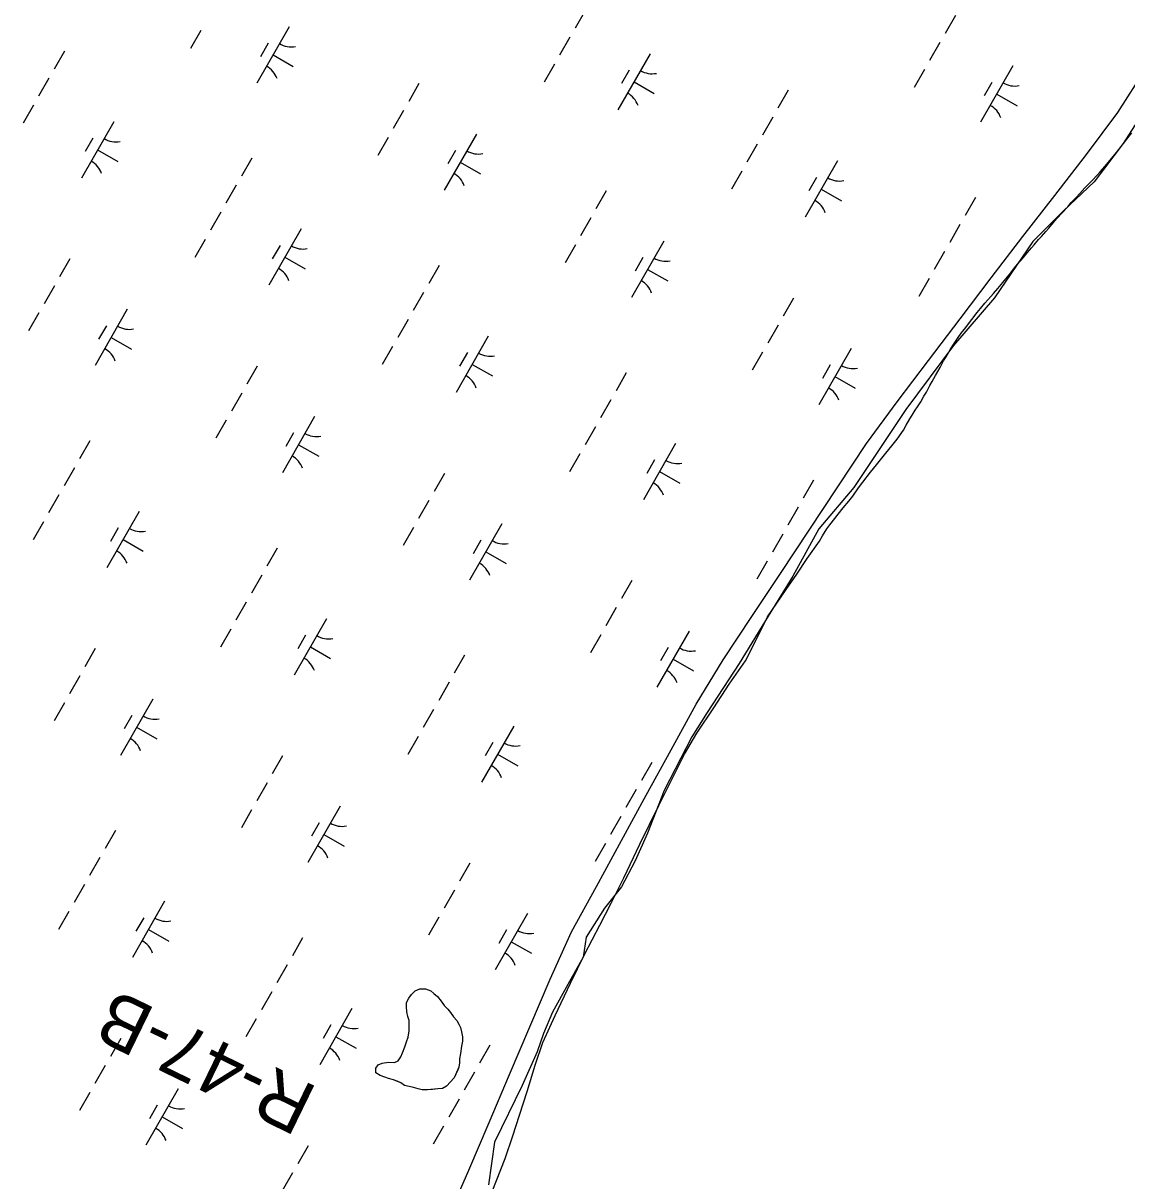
# Model space of a CAD drawing. Extents: x 3930721 to 3950824, y 220441 to 242861.
# Drawn here: x 3937569 to 3938420, y 226313 to 227205 of the extents above; entities that cross this region are included whole.
import ezdxf

# ---------------------------------------------------------------- set-up
doc = ezdxf.new("R2010")
doc.units = 0
for name, color, linetype in [('V-RIVR-EDGE', 7, 'Continuous'), ('V-RIVR-RANG-IDEN', 7, 'Continuous'), ('V-RRAP-FSHR', 7, 'Continuous'), ('V-TOPO-SHOR', 7, 'Continuous'), ('V-WETL-SWMP', 7, 'Continuous')]:
    doc.layers.add(name, color=color, linetype=linetype)

msp = doc.modelspace()

# ---------------------------------------------------------------- linework, layer by layer
at = {"layer": 'V-RIVR-EDGE'}
msp.add_lwpolyline([(3938454.68, 227171.4), (3938416.96, 227112.46), (3938394.57, 227083), (3938370.99, 227060.6), (3938347.42, 227037.03), (3938317.95, 226993.41), (3938286.13, 226956.87), (3938249.59, 226907.37), (3938209.51, 226847.25), (3938182.4, 226815.43), (3938162.36, 226778.89), (3938143.5, 226748.24), (3938121.11, 226711.7), (3938096.35, 226673.98), (3938084.57, 226655.12), (3938063.35, 226613.87), (3938050.38, 226580.86), (3938040.95, 226559.65), (3938030.34, 226539.61), (3938017.38, 226523.11), (3938003.23, 226500.71), (3938000.88, 226485.39), (3937989.09, 226464.17), (3937977.3, 226442.95), (3937970.23, 226426.45), (3937965.52, 226412.31), (3937953.73, 226386.38), (3937932.51, 226342.76), (3937927.8, 226309.76)], dxfattribs=at)
at = {"layer": 'V-RRAP-FSHR'}
msp.add_lwpolyline([(3937896.8, 226284.54), (3937912.71, 226321.23), (3937928.51, 226357.98), (3937944.13, 226394.8), (3937959.75, 226431.63), (3937975.38, 226468.45), (3937991.95, 226504.81), (3938011.14, 226539.91), (3938030.32, 226575.12), (3938049.5, 226610.11), (3938068.68, 226645.21), (3938087.86, 226680.31), (3938108.69, 226714.42), (3938130.77, 226747.78), (3938152.85, 226781.13), (3938174.93, 226814.49), (3938197.13, 226847.84), (3938219.1, 226881.18), (3938242.95, 226913.29), (3938266.92, 226945.32), (3938291.41, 226977.22), (3938315.4, 227008.95), (3938339.77, 227040.67), (3938364.23, 227072.32), (3938388.68, 227103.97), (3938412.83, 227136.41), (3938434.22, 227169.85)], dxfattribs=at)
at = {"layer": 'V-TOPO-SHOR'}
msp.add_lwpolyline([(3937895.57, 226385.81), (3937892.38, 226384.2), (3937888.78, 226383.8), (3937884.79, 226383.39), (3937880.79, 226382.98), (3937876.79, 226382.96), (3937873.59, 226383.76), (3937869.99, 226384.95), (3937866.79, 226385.74), (3937863.19, 226386.52), (3937860.39, 226388.52), (3937857.59, 226389.71), (3937854.79, 226390.9), (3937850.79, 226391.69), (3937847.99, 226392.88), (3937844.39, 226394.07), (3937841.19, 226396.06), (3937841.18, 226399.66), (3937842.77, 226402.46), (3937845.96, 226403.67), (3937850.76, 226404.48), (3937855.56, 226404.09), (3937858.35, 226405.3), (3937860.34, 226408.5), (3937861.53, 226411.7), (3937863.52, 226416.1), (3937864.7, 226420.1), (3937865.89, 226423.7), (3937866.68, 226428.5), (3937866.67, 226432.1), (3937866.66, 226436.49), (3937865.85, 226439.69), (3937865.04, 226443.29), (3937864.63, 226447.28), (3937864.62, 226450.48), (3937866.61, 226453.68), (3937868.6, 226456.49), (3937871.39, 226459.29), (3937874.99, 226460.9), (3937879.38, 226460.91), (3937883.38, 226459.32), (3937885.79, 226457.33), (3937888.59, 226454.94), (3937891.4, 226451.35), (3937893.81, 226448.16), (3937896.61, 226445.37), (3937898.62, 226442.58), (3937901.02, 226439.38), (3937903.43, 226436.59), (3937905.04, 226433.8), (3937906.24, 226431.01), (3937907.05, 226427.81), (3937907.86, 226423.82), (3937907.87, 226420.62), (3937907.08, 226416.62), (3937906.29, 226411.02), (3937905.51, 226407.02), (3937905.51, 226403.82), (3937905.12, 226400.62), (3937903.93, 226397.83), (3937902.74, 226395.02), (3937901.55, 226392.22), (3937895.57, 226385.81)], dxfattribs=at)
at = {"layer": 'V-WETL-SWMP'}
for p, q in [((3938002.57, 227215.37), (3937994.62, 227201.49)), ((3938287.74, 227211.08), (3938279.78, 227197.2)), ((3937706.14, 227199.66), (3937698.19, 227185.77)), ((3937774.26, 227202.47), (3937749.41, 227159.08)), ((3937758.12, 227189.82), (3937752.16, 227179.4)), ((3937990.64, 227194.54), (3937982.69, 227180.66)), ((3938275.81, 227190.25), (3938267.86, 227176.37)), ((3937601.1, 227183.76), (3937593.14, 227169.88)), ((3937761.84, 227180.78), (3937777.45, 227171.83)), ((3938052.47, 227181.7), (3938027.62, 227138.31)), ((3937978.71, 227173.72), (3937970.76, 227159.83)), ((3938036.33, 227169.04), (3938030.37, 227158.63)), ((3938263.88, 227169.43), (3938255.93, 227155.54)), ((3938332, 227172.24), (3938307.15, 227128.85)), ((3937589.17, 227162.93), (3937581.22, 227149.05)), ((3938040.04, 227160), (3938055.66, 227151.06)), ((3938315.86, 227159.59), (3938309.9, 227149.17)), ((3937874.33, 227158.64), (3937866.38, 227144.76)), ((3938158.84, 227153.53), (3938150.89, 227139.65)), ((3938319.58, 227150.55), (3938335.2, 227141.6)), ((3937577.24, 227142.11), (3937569.29, 227128.22)), ((3937862.41, 227137.82), (3937854.45, 227123.93)), ((3938146.91, 227132.7), (3938138.96, 227118.82)), ((3937639.07, 227129.26), (3937614.22, 227085.87)), ((3937622.93, 227116.61), (3937616.96, 227106.19)), ((3937850.48, 227116.99), (3937842.53, 227103.11)), ((3937918.6, 227119.8), (3937893.75, 227076.42)), ((3938417.25, 227112.51), (3938419.83, 227115.77)), ((3938419.83, 227115.77), (3938423.62, 227120.75)), ((3937626.64, 227107.57), (3937642.26, 227098.62)), ((3937902.46, 227107.15), (3937896.5, 227096.74)), ((3938134.98, 227111.88), (3938127.03, 227097.99)), ((3938409.34, 227102.39), (3938411.92, 227105.65)), ((3938411.92, 227105.65), (3938415.36, 227110.11)), ((3938415.36, 227110.11), (3938417.25, 227112.51)), ((3937745.44, 227101.09), (3937737.48, 227087.21)), ((3937906.18, 227098.11), (3937921.8, 227089.17)), ((3938196.81, 227099.03), (3938171.96, 227055.64)), ((3938402.98, 227094.84), (3938405.56, 227097.76)), ((3938405.56, 227097.76), (3938409.34, 227102.39)), ((3938123.06, 227091.05), (3938115.1, 227077.17)), ((3938393, 227083.86), (3938396.96, 227088.15)), ((3938396.96, 227088.15), (3938399.36, 227090.72)), ((3938399.36, 227090.72), (3938402.98, 227094.84)), ((3937733.51, 227080.27), (3937725.56, 227066.38)), ((3938180.67, 227086.38), (3938174.71, 227075.96)), ((3938387.5, 227078.2), (3938393, 227083.86)), ((3938018.68, 227075.98), (3938010.72, 227062.09)), ((3938184.39, 227077.34), (3938200, 227068.39)), ((3938303.18, 227070.86), (3938295.23, 227056.98)), ((3938376.84, 227066.88), (3938380.96, 227071.17)), ((3938380.96, 227071.17), (3938383.54, 227073.91)), ((3938383.54, 227073.91), (3938387.5, 227078.2)), ((3938369.96, 227059.16), (3938374.43, 227063.79)), ((3938374.43, 227063.79), (3938376.84, 227066.88)), ((3937721.58, 227059.44), (3937713.63, 227045.56)), ((3938006.75, 227055.15), (3937998.8, 227041.27)), ((3938363.42, 227051.62), (3938366, 227054.7)), ((3938366, 227054.7), (3938369.96, 227059.16)), ((3937783.41, 227046.59), (3937758.56, 227003.21)), ((3938291.25, 227050.04), (3938283.3, 227036.15)), ((3938353.96, 227040.81), (3938357.4, 227044.58)), ((3938357.4, 227044.58), (3938359.81, 227047.33)), ((3938359.81, 227047.33), (3938363.42, 227051.62)), ((3937709.65, 227038.61), (3937701.7, 227024.73)), ((3937994.82, 227034.33), (3937986.87, 227020.44)), ((3938062.94, 227037.14), (3938038.09, 226993.75)), ((3938346.39, 227032.06), (3938348.46, 227034.29)), ((3938348.46, 227034.29), (3938351.72, 227038.41)), ((3938351.72, 227038.41), (3938353.96, 227040.81)), ((3937767.27, 227033.94), (3937761.31, 227023.53)), ((3938279.32, 227029.21), (3938271.37, 227015.33)), ((3938339.86, 227024.34), (3938343.3, 227028.46)), ((3938343.3, 227028.46), (3938346.39, 227032.06)), ((3937605.27, 227023.54), (3937597.32, 227009.66)), ((3937770.98, 227024.9), (3937786.6, 227015.95)), ((3937889.78, 227018.43), (3937881.83, 227004.54)), ((3938046.8, 227024.49), (3938040.84, 227014.07)), ((3938332.46, 227015.59), (3938335.56, 227019.37)), ((3938335.56, 227019.37), (3938339.86, 227024.34)), ((3938050.52, 227015.44), (3938066.14, 227006.5)), ((3938267.4, 227008.38), (3938259.45, 226994.5)), ((3938324.2, 227005.3), (3938326.61, 227008.21)), ((3938326.61, 227008.21), (3938330.39, 227012.67)), ((3938330.39, 227012.67), (3938332.46, 227015.59)), ((3937593.35, 227002.72), (3937585.39, 226988.83)), ((3938317.15, 226996.89), (3938320.42, 227000.84)), ((3938320.42, 227000.84), (3938324.2, 227005.3)), ((3937877.85, 226997.6), (3937869.9, 226983.72)), ((3938163.02, 226993.31), (3938155.07, 226979.43)), ((3938310.44, 226989.52), (3938315.09, 226994.49)), ((3938315.09, 226994.49), (3938317.15, 226996.89)), ((3937581.42, 226981.89), (3937573.47, 226968.01)), ((3937649.54, 226984.7), (3937624.69, 226941.31)), ((3938300.29, 226976.82), (3938304.59, 226982.14)), ((3938304.59, 226982.14), (3938307, 226985.23)), ((3938307, 226985.23), (3938310.44, 226989.52)), ((3937633.4, 226972.05), (3937627.44, 226961.64)), ((3937865.92, 226976.77), (3937857.97, 226962.89)), ((3938151.09, 226972.49), (3938143.14, 226958.6)), ((3938295.82, 226970.64), (3938297.71, 226973.39)), ((3938297.71, 226973.39), (3938300.29, 226976.82)), ((3937637.12, 226963.01), (3937652.74, 226954.06)), ((3937927.75, 226963.93), (3937902.9, 226920.54)), ((3938286.18, 226957.43), (3938289.97, 226962.92)), ((3938289.97, 226962.92), (3938292.21, 226966.36)), ((3938292.21, 226966.36), (3938295.82, 226970.64)), ((3937854, 226955.95), (3937846.04, 226942.06)), ((3938207.28, 226954.47), (3938182.43, 226911.08)), ((3938283.95, 226953.83), (3938286.18, 226957.43)), ((3937911.61, 226951.27), (3937905.65, 226940.86)), ((3938139.16, 226951.66), (3938131.21, 226937.78)), ((3938278.44, 226944.91), (3938280.51, 226948.17)), ((3938280.51, 226948.17), (3938283.95, 226953.83)), ((3937749.62, 226940.88), (3937741.66, 226926.99)), ((3937915.33, 226942.23), (3937930.94, 226933.29)), ((3938191.15, 226941.82), (3938185.18, 226931.41)), ((3938272.41, 226933.75), (3938276.03, 226939.93)), ((3938276.03, 226939.93), (3938278.44, 226944.91)), ((3938034.12, 226935.76), (3938026.17, 226921.88)), ((3938194.86, 226932.78), (3938210.48, 226923.83)), ((3938268.11, 226925.86), (3938269.83, 226929.12)), ((3938269.83, 226929.12), (3938272.41, 226933.75)), ((3937737.69, 226920.05), (3937729.74, 226906.17)), ((3938263.46, 226917.62), (3938265.36, 226920.71)), ((3938265.36, 226920.71), (3938268.11, 226925.86)), ((3938022.19, 226914.93), (3938014.24, 226901.05)), ((3938256.75, 226906.98), (3938258.47, 226909.55)), ((3938258.47, 226909.55), (3938261.05, 226913.33)), ((3938261.05, 226913.33), (3938263.46, 226917.62)), ((3937793.88, 226902.04), (3937769.03, 226858.65)), ((3938252.62, 226900.29), (3938254.34, 226903.03)), ((3938254.34, 226903.03), (3938256.75, 226906.98)), ((3937725.76, 226899.22), (3937717.81, 226885.34)), ((3938010.26, 226894.11), (3938002.31, 226880.22)), ((3938242.81, 226884.67), (3938247.63, 226891.54)), ((3938247.63, 226891.54), (3938249.87, 226895.31)), ((3938249.87, 226895.31), (3938252.62, 226900.29)), ((3937620.72, 226883.32), (3937612.77, 226869.44)), ((3937777.74, 226889.38), (3937771.78, 226878.97)), ((3938238.85, 226879.35), (3938242.81, 226884.67)), ((3937781.46, 226880.34), (3937797.08, 226871.4)), ((3938072.09, 226881.26), (3938047.24, 226837.87)), ((3938226.98, 226864.77), (3938234.21, 226873.86)), ((3938234.21, 226873.86), (3938238.85, 226879.35)), ((3937998.34, 226873.28), (3937990.39, 226859.4)), ((3938055.95, 226868.61), (3938049.99, 226858.2)), ((3938222.34, 226859.11), (3938226.98, 226864.77)), ((3937608.79, 226862.5), (3937600.84, 226848.61)), ((3937893.96, 226858.21), (3937886, 226844.33)), ((3938059.67, 226859.57), (3938075.29, 226850.62)), ((3938216.32, 226851.56), (3938222.34, 226859.11)), ((3938178.46, 226853.1), (3938170.51, 226839.21)), ((3938208.58, 226840.75), (3938213.05, 226847.1)), ((3938213.05, 226847.1), (3938216.32, 226851.56)), ((3937596.86, 226841.67), (3937588.91, 226827.79)), ((3938205.65, 226836.81), (3938208.58, 226840.75)), ((3937882.03, 226837.38), (3937874.08, 226823.5)), ((3938166.53, 226832.27), (3938158.58, 226818.38)), ((3938197.4, 226826.69), (3938201.18, 226831.66)), ((3938201.18, 226831.66), (3938205.65, 226836.81)), ((3937584.94, 226820.85), (3937576.98, 226806.96)), ((3937658.69, 226828.82), (3937633.84, 226785.44)), ((3938190.86, 226818.45), (3938194.81, 226823.43)), ((3938194.81, 226823.43), (3938197.4, 226826.69)), ((3937642.55, 226816.17), (3937636.59, 226805.76)), ((3937870.1, 226816.56), (3937862.15, 226802.67)), ((3937938.22, 226819.37), (3937913.37, 226775.98)), ((3938154.61, 226811.44), (3938146.65, 226797.56)), ((3938185.35, 226810.04), (3938188.62, 226815.53)), ((3938188.62, 226815.53), (3938190.86, 226818.45)), ((3937646.26, 226807.13), (3937661.88, 226798.19)), ((3937922.09, 226806.72), (3937916.12, 226796.3)), ((3938173.48, 226792.53), (3938182.98, 226806.06)), ((3938182.98, 226806.06), (3938185.35, 226810.04)), ((3937765.06, 226800.66), (3937757.11, 226786.77)), ((3937925.8, 226797.68), (3937941.42, 226788.73)), ((3938142.68, 226790.62), (3938134.73, 226776.73)), ((3938165.56, 226780.58), (3938173.48, 226792.53)), ((3937753.13, 226779.83), (3937745.18, 226765.95)), ((3938038.3, 226775.54), (3938030.35, 226761.66)), ((3938157.25, 226768.64), (3938165.56, 226780.58)), ((3938143, 226747.54), (3938157.25, 226768.64)), ((3937741.2, 226759.01), (3937733.25, 226745.12)), ((3938026.37, 226754.72), (3938018.42, 226740.83)), ((3937803.03, 226746.16), (3937778.18, 226702.77)), ((3938134.3, 226730.03), (3938143, 226747.54)), ((3937729.28, 226738.18), (3937721.33, 226724.3)), ((3937786.89, 226733.51), (3937780.93, 226723.09)), ((3938014.44, 226733.89), (3938006.49, 226720.01)), ((3938082.57, 226736.7), (3938057.72, 226693.32)), ((3937624.9, 226723.11), (3937616.94, 226709.22)), ((3937790.61, 226724.46), (3937806.23, 226715.52)), ((3938066.43, 226724.05), (3938060.46, 226713.64)), ((3938126, 226713.72), (3938134.3, 226730.03)), ((3937909.4, 226717.99), (3937901.45, 226704.11)), ((3938070.14, 226715.01), (3938085.76, 226706.06)), ((3938113.33, 226695.8), (3938126, 226713.72)), ((3937612.97, 226702.28), (3937605.02, 226688.4)), ((3937897.47, 226697.17), (3937889.52, 226683.28)), ((3938101.46, 226677.49), (3938113.33, 226695.8)), ((3937601.04, 226681.45), (3937593.09, 226667.57)), ((3937669.16, 226684.27), (3937644.31, 226640.88)), ((3938088.4, 226657.98), (3938101.46, 226677.49)), ((3937653.03, 226671.61), (3937647.06, 226661.2)), ((3937885.55, 226676.34), (3937877.59, 226662.46)), ((3937656.74, 226662.57), (3937672.36, 226653.63)), ((3937947.37, 226663.49), (3937922.52, 226620.1)), ((3937873.62, 226655.51), (3937865.67, 226641.63)), ((3937931.23, 226650.84), (3937925.27, 226640.43)), ((3938078.91, 226641.67), (3938088.4, 226657.98)), ((3937934.95, 226641.8), (3937950.57, 226632.85)), ((3938069.03, 226621.77), (3938078.91, 226641.67)), ((3937769.24, 226640.44), (3937761.29, 226626.56)), ((3938053.74, 226635.33), (3938045.79, 226621.44)), ((3937757.31, 226619.62), (3937749.36, 226605.73)), ((3938059.14, 226602.27), (3938069.03, 226621.77)), ((3938041.81, 226614.5), (3938033.86, 226600.62)), ((3937745.38, 226598.79), (3937737.43, 226584.9)), ((3937813.5, 226601.6), (3937788.66, 226558.21)), ((3938044.52, 226572.43), (3938059.14, 226602.27)), ((3937797.37, 226588.95), (3937791.4, 226578.54)), ((3938029.89, 226593.67), (3938021.94, 226579.79)), ((3937640.34, 226582.89), (3937632.39, 226569.01)), ((3937801.08, 226579.91), (3937816.7, 226570.96)), ((3938017.96, 226572.85), (3938010.01, 226558.96)), ((3938032.27, 226546.57), (3938044.52, 226572.43)), ((3937628.41, 226562.06), (3937620.46, 226548.18)), ((3937913.58, 226557.78), (3937905.63, 226543.89)), ((3938022.39, 226527.07), (3938032.27, 226546.57)), ((3937616.49, 226541.24), (3937608.53, 226527.35)), ((3937901.65, 226536.95), (3937893.7, 226523.06)), ((3937678.31, 226528.39), (3937653.46, 226485)), ((3938013.69, 226509.96), (3938022.39, 226527.07)), ((3937604.56, 226520.41), (3937596.61, 226506.53)), ((3937957.85, 226518.94), (3937933, 226475.55)), ((3937662.17, 226515.74), (3937656.21, 226505.32)), ((3937889.72, 226516.12), (3937881.77, 226502.24)), ((3938001.83, 226487.28), (3938013.69, 226509.96)), ((3937665.89, 226506.7), (3937681.51, 226497.75)), ((3937784.68, 226500.22), (3937776.73, 226486.34)), ((3937941.71, 226506.28), (3937935.74, 226495.87)), ((3937945.42, 226497.24), (3937961.04, 226488.3)), ((3937991.16, 226465.39), (3938001.83, 226487.28)), ((3937772.75, 226479.4), (3937764.8, 226465.51)), ((3937979.31, 226440.33), (3937991.16, 226465.39)), ((3937760.83, 226458.57), (3937752.88, 226444.69)), ((3937866.61, 226453.68), (3937868.6, 226456.48)), ((3937868.6, 226456.48), (3937871.39, 226459.29)), ((3937871.39, 226459.29), (3937874.99, 226460.9)), ((3937874.99, 226460.9), (3937879.38, 226460.91)), ((3937879.38, 226460.91), (3937883.38, 226459.32)), ((3937883.38, 226459.32), (3937885.79, 226457.33)), ((3937885.79, 226457.33), (3937888.59, 226454.94)), ((3937888.59, 226454.94), (3937891.4, 226451.35)), ((3937822.65, 226445.72), (3937797.8, 226402.34)), ((3937864.62, 226450.48), (3937866.61, 226453.68)), ((3937864.63, 226447.28), (3937864.62, 226450.48)), ((3937865.04, 226443.29), (3937864.63, 226447.28)), ((3937891.4, 226451.35), (3937893.81, 226448.16)), ((3937893.81, 226448.16), (3937896.61, 226445.37)), ((3937896.61, 226445.37), (3937898.62, 226442.58)), ((3937748.9, 226437.75), (3937740.95, 226423.86)), ((3937865.85, 226439.69), (3937865.04, 226443.29)), ((3937866.66, 226436.5), (3937865.85, 226439.69)), ((3937866.68, 226428.5), (3937866.66, 226436.5)), ((3937898.62, 226442.58), (3937901.02, 226439.38)), ((3937901.02, 226439.38), (3937903.43, 226436.59)), ((3937903.43, 226436.59), (3937905.03, 226433.8)), ((3937969.83, 226419.64), (3937979.31, 226440.33)), ((3937806.52, 226433.07), (3937800.55, 226422.66)), ((3937865.89, 226423.7), (3937866.68, 226428.5)), ((3937905.03, 226433.8), (3937906.24, 226431.01)), ((3937906.24, 226431.01), (3937907.05, 226427.81)), ((3937907.05, 226427.81), (3937907.86, 226423.82)), ((3937644.52, 226422.67), (3937636.57, 226408.79)), ((3937810.23, 226424.03), (3937825.85, 226415.08)), ((3937863.52, 226416.1), (3937864.7, 226420.1)), ((3937864.7, 226420.1), (3937865.89, 226423.7)), ((3937907.87, 226420.62), (3937907.08, 226416.62)), ((3937907.86, 226423.82), (3937907.87, 226420.62)), ((3937963.91, 226402.14), (3937969.83, 226419.64)), ((3937860.34, 226408.5), (3937861.53, 226411.7)), ((3937861.53, 226411.7), (3937863.52, 226416.1)), ((3937906.29, 226411.02), (3937905.51, 226407.02)), ((3937907.08, 226416.62), (3937906.29, 226411.02)), ((3937929.02, 226417.56), (3937921.07, 226403.67)), ((3937632.59, 226401.85), (3937624.64, 226387.96)), ((3937841.18, 226399.66), (3937842.77, 226402.46)), ((3937842.77, 226402.46), (3937845.96, 226403.67)), ((3937845.96, 226403.67), (3937850.76, 226404.48)), ((3937850.76, 226404.48), (3937855.55, 226404.09)), ((3937855.55, 226404.09), (3937858.35, 226405.3)), ((3937858.35, 226405.3), (3937860.34, 226408.5)), ((3937905.12, 226400.63), (3937901.55, 226392.22)), ((3937905.51, 226403.83), (3937905.12, 226400.63)), ((3937905.51, 226407.02), (3937905.51, 226403.83)), ((3937957.61, 226381.86), (3937963.91, 226402.14)), ((3937841.19, 226396.06), (3937841.18, 226399.66)), ((3937844.39, 226394.07), (3937841.19, 226396.06)), ((3937847.99, 226392.88), (3937844.39, 226394.07)), ((3937850.79, 226391.69), (3937847.99, 226392.88)), ((3937854.79, 226390.9), (3937850.79, 226391.69)), ((3937901.55, 226392.22), (3937895.57, 226385.81)), ((3937917.1, 226396.73), (3937909.14, 226382.85)), ((3937688.79, 226383.83), (3937663.94, 226340.44)), ((3937860.39, 226388.52), (3937854.79, 226390.9)), ((3937863.19, 226386.52), (3937860.39, 226388.52)), ((3937866.79, 226385.74), (3937863.19, 226386.52)), ((3937869.99, 226384.95), (3937866.79, 226385.74)), ((3937873.59, 226383.76), (3937869.99, 226384.95)), ((3937876.79, 226382.96), (3937873.59, 226383.76)), ((3937880.79, 226382.98), (3937876.79, 226382.96)), ((3937888.78, 226383.8), (3937880.79, 226382.98)), ((3937892.38, 226384.21), (3937888.78, 226383.8)), ((3937895.57, 226385.81), (3937892.38, 226384.21)), ((3937620.66, 226381.02), (3937612.71, 226367.14)), ((3937905.17, 226375.91), (3937897.22, 226362.02)), ((3937951.7, 226363.56), (3937957.61, 226381.86)), ((3937672.65, 226371.18), (3937666.68, 226360.77)), ((3937676.36, 226362.14), (3937691.98, 226353.19)), ((3937946.57, 226347.65), (3937951.7, 226363.56)), ((3937893.24, 226355.08), (3937885.29, 226341.19)), ((3937940.66, 226330.15), (3937946.57, 226347.65)), ((3937788.86, 226340.01), (3937780.91, 226326.12)), ((3937930.79, 226304.69), (3937940.66, 226330.15)), ((3937776.93, 226319.18), (3937768.98, 226305.3))]:
    msp.add_line(p, q, dxfattribs=at)
for centre, start, end in [((3937775.77, 227204.63), 239.42788, 280.97154), ((3937748.31, 227156.69), 19.42788, 60.97154), ((3938053.98, 227183.85), 239.42788, 280.97154), ((3938333.51, 227174.4), 239.42788, 280.97154), ((3938026.52, 227135.92), 19.42788, 60.97154), ((3938306.06, 227126.46), 19.42788, 60.97154), ((3937640.58, 227131.42), 239.42788, 280.97154), ((3937920.11, 227121.96), 239.42788, 280.97154), ((3937613.12, 227083.48), 19.42788, 60.97154), ((3937892.66, 227074.02), 19.42788, 60.97154), ((3938198.32, 227101.19), 239.42788, 280.97154), ((3938170.86, 227053.25), 19.42788, 60.97154), ((3937784.92, 227048.75), 239.42788, 280.97154), ((3938064.45, 227039.3), 239.42788, 280.97154), ((3937757.46, 227000.81), 19.42788, 60.97154), ((3938037, 226991.36), 19.42788, 60.97154), ((3937651.05, 226986.86), 239.42788, 280.97154), ((3937623.6, 226938.92), 19.42788, 60.97154), ((3937929.26, 226966.08), 239.42788, 280.97154), ((3938208.79, 226956.63), 239.42788, 280.97154), ((3937901.8, 226918.15), 19.42788, 60.97154), ((3938181.34, 226908.69), 19.42788, 60.97154), ((3937795.39, 226904.19), 239.42788, 280.97154), ((3937767.94, 226856.26), 19.42788, 60.97154), ((3938073.6, 226883.42), 239.42788, 280.97154), ((3938046.15, 226835.48), 19.42788, 60.97154), ((3937660.2, 226830.98), 239.42788, 280.97154), ((3937939.73, 226821.53), 239.42788, 280.97154), ((3937632.74, 226783.04), 19.42788, 60.97154), ((3937912.28, 226773.59), 19.42788, 60.97154), ((3937804.54, 226748.32), 239.42788, 280.97154), ((3938084.07, 226738.86), 239.42788, 280.97154), ((3937777.09, 226700.38), 19.42788, 60.97154), ((3938056.62, 226690.92), 19.42788, 60.97154), ((3937670.67, 226686.42), 239.42788, 280.97154), ((3937643.22, 226638.49), 19.42788, 60.97154), ((3937948.88, 226665.65), 239.42788, 280.97154), ((3937921.43, 226617.71), 19.42788, 60.97154), ((3937815.01, 226603.76), 239.42788, 280.97154), ((3937787.56, 226555.82), 19.42788, 60.97154), ((3937679.82, 226530.55), 239.42788, 280.97154), ((3937959.36, 226521.09), 239.42788, 280.97154), ((3937652.37, 226482.61), 19.42788, 60.97154), ((3937931.9, 226473.15), 19.42788, 60.97154), ((3937824.16, 226447.88), 239.42788, 280.97154), ((3937796.71, 226399.94), 19.42788, 60.97154), ((3937690.3, 226385.99), 239.42788, 280.97154), ((3937662.84, 226338.05), 19.42788, 60.97154)]:
    msp.add_arc(centre, 17.62, start, end, dxfattribs=at)

# ---------------------------------------------------------------- texts
at = {"layer": 'V-RIVR-RANG-IDEN'}
msp.add_text('R-47-B', height=41.5, rotation=154.0692, dxfattribs=at).set_placement((3937797.62, 226384.33))

doc.saveas('drawing.dxf')
